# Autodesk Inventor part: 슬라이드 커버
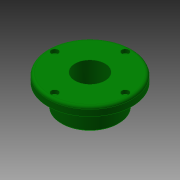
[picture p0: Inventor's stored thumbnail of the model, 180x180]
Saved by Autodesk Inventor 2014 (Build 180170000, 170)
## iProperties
Created: 2015-10
Part Number: 슬라이드 커버
Document SubType Name: Modeling
Designer: mdu
Density: 7.86 g/cm^3
Material: 강철, 연강
Mass: 598.523 g
Surface Area: 229.996 cm^2
Volume: 76.148 cm^3
Appearance: 진녹색
Author: mdu
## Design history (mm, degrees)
sketch "스케치1"
  geometry: C1 r 47.5 at (0, 0); C2 r 32.5 at (0, 0); 1 further point
  constraints: 2 centre point, 2 coincident
  dimensions: "d33" = 95 diameter of C1; "d35" = 65 diameter of C2
extrude "돌출1" new body sketch "스케치1" distance "d0" = 10; taper "d1" = 0 deg
extrude "돌출2" join sketch "스케치1" distance "d2" = 25; taper "d3" = 0 deg
hole "구멍1" diameter "d6" = 36; stored, may be unused: countersink angle "d10" = 90 deg, drill point angle "d12" = 118 deg; dims "d7" = 6, "d8" = 4, "d9" = 2, "d11" = 8, "d41" = 10, "d42" = 10
sketch "스케치2" dims "d36" = 80
  geometry: 4 further points
  constraints: 2 coincident, 2 vertical alignment, 2 other
hole "구멍2" sketch "스케치2" at (0, 40) diameter "d13" = 4.5; stored, may be unused: countersink angle "d17" = 90 deg, drill point angle "d19" = 118 deg; dims "d14" = 6, "d15" = 8, "d16" = 4.4, "d18" = 8
fillet "모깎기1" dims "d23" = 3
chamfer "모따기1" distance "d24" = 1; stored, may be unused: second distance "d25" = 2, angle "d26" = 45 deg
sketch "스케치3"
  geometry: C1 r 26 at (0, 0); C2 r 19 at (0, 0) reference; 1 further point
  constraints: 1 centre point, 1 concentric
  dimensions: "d27" = 52 diameter of C1
extrude "돌출3" cut sketch "스케치3" distance "d28" = 10; taper "d29" = 0 deg
chamfer "모따기2" distance "d30" = 1; stored, may be unused: second distance "d31" = 2, angle "d32" = 45 deg
node "솔리드1"
pattern_circular "원형 패턴1" dims angle "d21" = 360 deg
